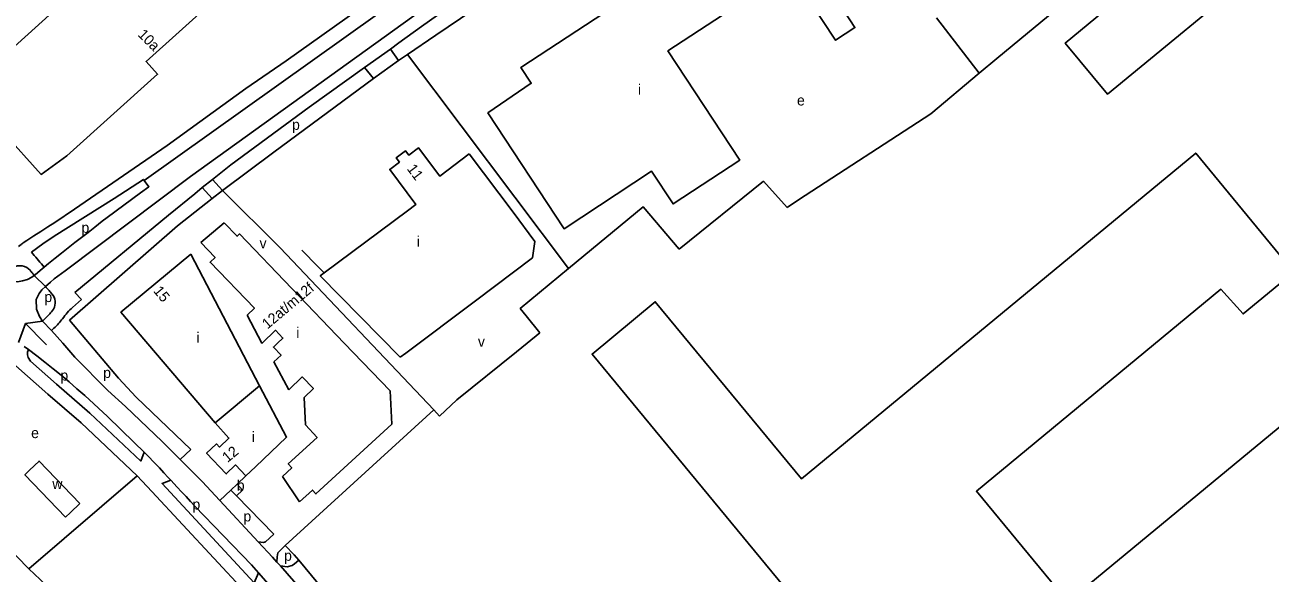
# Model space of a CAD drawing. Extents: x 156097 to 158136, y 385644 to 388348.
# Drawn here: x 156955.8 to 157432.4, y 387161.9 to 387371.8 of the extents above; entities that cross this region are included whole.
import ezdxf

# ---------------------------------------------------------------- set-up
doc = ezdxf.new("R2010")
doc.units = 0
for name, color, linetype in [('BLT_Basislijn', 7, 'Continuous'), ('BLT_Bebouwing', 7, 'Continuous'), ('BLT_Centroide', 7, 'Continuous'), ('BLT_Huisnummer', 7, 'Continuous'), ('BLT_Huisnummer_reeks', 7, 'Continuous'), ('BLT_Onderverdeling_panden', 7, 'Continuous'), ('BLT_Vlakafsluiter', 7, 'Continuous')]:
    doc.layers.add(name, color=color, linetype=linetype)

msp = doc.modelspace()

# ---------------------------------------------------------------- linework, layer by layer
at = {"layer": 'BLT_Basislijn'}
for p, q in [((157411.2, 387428.05), (157327.73, 387358.89)), ((157304.64, 387374.52), (157321.05, 387353.28)), ((157095.67, 387362.5), (157098.81, 387358.08)), ((157102.2, 387360.43), (157163.89, 387278.49)), ((157327.73, 387358.89), (157321.05, 387353.28)), ((157089.23, 387351.22), (157085.74, 387355.5)), ((157321.05, 387353.28), (157302.57, 387337.73)), ((157040.36, 387347.36), (157010.26, 387325.6)), ((157034.53, 387318.15), (157064.57, 387340.26)), ((157251.84, 387304.78), (157302.57, 387337.73)), ((157034.53, 387318.15), (157027.57, 387312.6)), ((157031.44, 387308.36), (157027.57, 387312.6)), ((157206.21, 387285.89), (157238.48, 387311.91)), ((157247.52, 387301.86), (157238.48, 387311.91)), ((157027.5, 387305.26), (157023.66, 387309.47)), ((157027.5, 387305.26), (157031.44, 387308.36)), ((157014.19, 387294.79), (157027.5, 387305.26)), ((157251.84, 387304.78), (157247.52, 387301.86)), ((156972.87, 387258.73), (157014.19, 387294.79)), ((156974.9, 387269.33), (156977.43, 387266.61)), ((157147.6, 387260.39), (157152.82, 387253.94)), ((156963.37, 387250), (156956.03, 387257.5)), ((157152.82, 387253.94), (157148.01, 387250)), ((156964.05, 387249.3), (156963.37, 387250)), ((157015.19, 387205.43), (157008.28, 387212.34)), ((156998.75, 387199.18), (157004.35, 387193.14)), ((157004.35, 387193.14), (157039.88, 387154.84)), ((157051.01, 387176.88), (157036.71, 387191.47)), ((157020.84, 387187.54), (157042.5, 387165.08)), ((157045.08, 387173.87), (157050.48, 387168.05)), ((157050.48, 387168.05), (157052.22, 387166.16)), ((157052.22, 387166.16), (157053.57, 387164.69)), ((157053.57, 387164.69), (157070.1, 387145.87)), ((157072.09, 387152.95), (157060.55, 387166.84))]:
    msp.add_line(p, q, dxfattribs=at)
for points in [[(156963.63, 387271.61), (156965.52, 387273.26), (156967.02, 387274.57), (156971.22, 387277.65), (157019.2, 387313.75), (157135.95, 387397.88), (157205.86, 387444.09), (157219.58, 387453.58), (157239.86, 387466.53), (157269.96, 387483.84), (157285.4, 387492.24)], [(157217.75, 387438.96), (157266.03, 387365.91), (157273.46, 387370.72), (157258.79, 387393.39), (157280.49, 387407.43)], [(157142.41, 387395.65), (157130.75, 387387.73), (157107.59, 387371.12)], [(157040.36, 387347.36), (157055.77, 387358.06), (157101.56, 387390.65)], [(157102.2, 387360.43), (157113.08, 387367.85), (157146.09, 387390.27)], [(157001.46, 387312.19), (157103.63, 387385.12)], [(157107.59, 387371.12), (157098.91, 387364.9)], [(157095.67, 387362.5), (157085.74, 387355.5)], [(157098.91, 387364.9), (157095.67, 387362.5)], [(157089.23, 387351.22), (157098.81, 387358.08)], [(157098.81, 387358.08), (157102.2, 387360.43)], [(157085.74, 387355.5), (157064.57, 387340.26)], [(157031.44, 387308.36), (157051.09, 387323.03), (157089.23, 387351.22)], [(157010.26, 387325.6), (156974.7, 387301.25), (156967.17, 387296.15)], [(156958.26, 387284.77), (156962.63, 387287.92), (156967.02, 387290.9), (156989.97, 387305.26), (157001.13, 387312.64), (157001.46, 387312.19)], [(157001.46, 387312.19), (157003.22, 387309.84), (157000, 387307.49), (156987.27, 387297.99), (156985.28, 387296.58), (156982.55, 387294.3)], [(157023.66, 387309.47), (157027.57, 387312.6)], [(157010.78, 387298.93), (157020.74, 387307.13), (157023.66, 387309.47)], [(157031.44, 387308.36), (157053.42, 387286.46), (157112.23, 387224.4)], [(157163.89, 387278.49), (157192.41, 387302.06), (157206.21, 387285.89)], [(156953.35, 387286.9), (156954.34, 387287.72), (156954.58, 387287.92), (156954.81, 387288.11), (156955.05, 387288.3), (156956.5, 387289.26), (156959.17, 387290.98), (156961.84, 387292.71), (156964.5, 387294.43), (156967.17, 387296.15)], [(156974.9, 387269.33), (157010.78, 387298.93)], [(156963.15, 387279.01), (156964.82, 387280.39), (156967.31, 387282.42), (156969.82, 387284.45), (156972.34, 387286.45), (156974.88, 387288.44), (156977.42, 387290.41), (156979.98, 387292.36), (156982.55, 387294.3)], [(156963.15, 387279.01), (156962.61, 387279.65), (156962.07, 387280.29), (156961.52, 387280.93), (156960.98, 387281.57), (156960.43, 387282.21), (156959.89, 387282.85), (156959.35, 387283.49), (156958.8, 387284.13), (156958.26, 387284.77)], [(157061.82, 387285.58), (157067.85, 387279.3), (157070.04, 387277.14)], [(156950.64, 387278.37), (156951.29, 387278.85), (156952.06, 387279.23), (156952.92, 387279.49), (156953.83, 387279.59), (156954.75, 387279.52), (156955.63, 387279.28), (156956.44, 387278.9), (156957.14, 387278.4), (156957.72, 387277.83)], [(156959.36, 387275.9), (156959.19, 387276.09), (156959.01, 387276.31), (156958.82, 387276.52), (156958.64, 387276.74), (156958.45, 387276.96), (156958.27, 387277.18), (156958.09, 387277.39), (156957.9, 387277.61), (156957.72, 387277.83)], [(156959.87, 387276.27), (156962.34, 387278.34), (156963.15, 387279.01)], [(157070.04, 387277.14), (157070.34, 387276.85)], [(157147.6, 387260.39), (157145.34, 387263.17), (157163.89, 387278.49)], [(156959.36, 387275.9), (156958.42, 387275.22), (156956.74, 387274.36), (156954.9, 387273.76), (156952.94, 387273.47), (156950.95, 387273.5), (156949, 387273.86), (156947.18, 387274.51), (156946.63, 387274.81)], [(156959.87, 387276.27), (156959.36, 387275.9)], [(156962.51, 387258.41), (156961.34, 387260.16), (156960.16, 387263.01), (156960.12, 387266.63), (156961.18, 387268.97), (156962.24, 387270.34), (156963.63, 387271.61)], [(156963.63, 387271.61), (156963.91, 387271.3), (156964.18, 387270.99), (156964.46, 387270.68), (156964.73, 387270.37), (156965.01, 387270.06), (156965.28, 387269.75), (156965.56, 387269.44), (156965.83, 387269.13), (156966.11, 387268.82)], [(156966.29, 387262.41), (156966.7, 387263.01), (156967.03, 387263.7), (156967.25, 387264.45), (156967.36, 387265.24), (156967.34, 387266.05), (156967.18, 387266.84), (156966.92, 387267.57), (156966.55, 387268.24), (156966.11, 387268.82)], [(156966.29, 387262.41), (156965.96, 387261.99), (156965.61, 387261.58), (156965.27, 387261.18), (156964.91, 387260.78), (156964.54, 387260.39), (156964.17, 387260), (156963.8, 387259.62), (156963.41, 387259.25), (156962.51, 387258.41)], [(156970.19, 387259.28), (156970.66, 387259.95), (156971.08, 387260.52), (156971.52, 387261.07), (156971.98, 387261.61), (156972.45, 387262.14), (156972.94, 387262.65), (156973.45, 387263.14), (156973.98, 387263.63), (156977.43, 387266.61)], [(156965.89, 387254.73), (156962.51, 387258.41)], [(156970.19, 387259.28), (156969.83, 387258.83), (156969.43, 387258.35), (156969.02, 387257.87), (156968.6, 387257.41), (156968.18, 387256.95), (156967.74, 387256.5), (156967.3, 387256.06), (156966.86, 387255.63), (156965.89, 387254.73)], [(157019.26, 387209.27), (156998.36, 387229.23), (156991.62, 387236.5), (156972.87, 387258.73)], [(156970.23, 387250), (156965.89, 387254.73)], [(156957.1, 387247.46), (156955.43, 387248.68)], [(156987.49, 387231.8), (156974.86, 387244.61), (156970.23, 387250)], [(157148.01, 387250), (157143.89, 387246.63), (157121.11, 387228.22)], [(156957.1, 387247.46), (156956.78, 387246.51), (156956.73, 387245.46), (156956.99, 387244.44), (156957.86, 387243)], [(156978.64, 387229.87), (156975.67, 387232.5), (156972.66, 387235.1), (156969.62, 387237.65), (156966.54, 387240.17), (156963.42, 387242.64), (156960.28, 387245.07), (156957.1, 387247.46)], [(156952.26, 387241.27), (156964.56, 387230.45), (156977.28, 387219.48), (156998.75, 387199.18)], [(156957.86, 387243), (156967.85, 387234.22), (156980.63, 387223.19), (157000.08, 387204.8), (157001.41, 387208.19)], [(156978.64, 387229.87), (156987.34, 387221.9), (156992.52, 387216.95), (156997.64, 387211.95), (157001.41, 387208.19)], [(156987.49, 387231.8), (156994.29, 387225.72), (157008.28, 387212.34)], [(157055.33, 387172.47), (157112.23, 387224.4)], [(157112.23, 387224.4), (157114.47, 387222.04)], [(157121.11, 387228.22), (157114.47, 387222.04)], [(156915.13, 387206.65), (156957.32, 387163.53)], [(157001.41, 387208.19), (157002.71, 387206.89), (157005.52, 387204.03)], [(157019.26, 387209.27), (157015.19, 387205.43)], [(157015.19, 387205.43), (157023.65, 387196.98), (157030.37, 387189.73)], [(157005.52, 387204.03), (157007.23, 387202.2), (157008.93, 387200.36), (157010.63, 387198.53), (157011.56, 387197.53)], [(156957.32, 387163.53), (156998.75, 387199.18)], [(157011.56, 387197.53), (157008.29, 387196.25), (157043.55, 387158.24), (157045.22, 387162)], [(157011.56, 387197.53), (157014.04, 387194.87), (157015.74, 387193.03), (157017.44, 387191.2), (157019.14, 387189.37), (157020.84, 387187.54)], [(157037.05, 387195.93), (157040.37, 387199.16)], [(157030.37, 387189.73), (157034.64, 387193.66)], [(157030.37, 387189.73), (157045.08, 387173.87)], [(157045.08, 387173.87), (157047.14, 387173.66), (157047.85, 387173.89), (157051.01, 387176.88)], [(157052.22, 387166.16), (157052.28, 387168.18), (157052.57, 387169.63), (157055.33, 387172.47)], [(157060.55, 387166.84), (157058.87, 387168.87), (157055.33, 387172.47)], [(156994.69, 387126.94), (156983.23, 387139.01), (156957.32, 387163.53)], [(157042.5, 387165.08), (157045.22, 387162)], [(157053.57, 387164.69), (157056.18, 387164.3), (157058.04, 387164.79), (157059, 387165.54), (157060.55, 387166.84)], [(157045.22, 387162), (157051.6, 387154.78), (157054.58, 387151.36)]]:
    msp.add_lwpolyline(points, dxfattribs=at)
at = {"layer": 'BLT_Bebouwing'}
for p, q in [((157125.84, 387322.42), (157142.64, 387300.06)), ((157031.99, 387296.02), (157023.07, 387288.52)), ((157040.83, 387260.62), (157046.4, 387250)), ((157046.45, 387249.92), (157046.4, 387250)), ((157046.45, 387249.92), (157046.53, 387250)), ((157101.53, 387246.13), (157099.41, 387244.54)), ((157056.72, 387232.04), (157051.03, 387242.78)), ((157063.17, 387218.74), (157062.65, 387229.2)), ((157034.64, 387193.66), (157037.05, 387195.93)), ((157060.92, 387189.24), (157054.3, 387198.96)), ((157036.71, 387191.47), (157034.64, 387193.66))]:
    msp.add_line(p, q, dxfattribs=at)
for points in [[(157038.09, 387441.53), (156933.03, 387346.62), (156962.04, 387314.53), (156971.84, 387321.61), (157006.52, 387352.89), (157002.13, 387357.76), (157041.29, 387393.15), (157053.38, 387379.77), (157072.5, 387393.4)], [(157218.51, 387427.55), (157243.69, 387389.24), (157201.91, 387361.79), (157229.36, 387320), (157203.83, 387303.22), (157195.6, 387315.75), (157162.16, 387293.75), (157132.98, 387338.1), (157149.58, 387349.4), (157145.56, 387355.42), (157216.58, 387402.06), (157206.77, 387417.03), (157210.94, 387419.78), (157209.65, 387421.72)], [(157414.82, 387415.14), (157353.98, 387364.8), (157370.14, 387345.19), (157431.01, 387395.44)], [(157330.32, 387055.02), (157369.92, 387087.72), (157362.29, 387096.97), (157371.11, 387104.35), (157372.36, 387102.86), (157374.45, 387102.96), (157376.12, 387102.26), (157377.56, 387100.99), (157378.05, 387099.5), (157384.37, 387104.72), (157379.21, 387110.93), (157469.96, 387185.87), (157477.56, 387176.69), (157497.38, 387193.06), (157460.35, 387237.99), (157354.89, 387150.97), (157319.99, 387193.25), (157413.54, 387270.58), (157422.05, 387261.11), (157441.45, 387277.16), (157403.93, 387322.7), (157252.98, 387198.06), (157197.06, 387265.8), (157172.83, 387245.77)]]:
    msp.add_lwpolyline(points, close=True, dxfattribs=at)
for points in [[(157070.34, 387276.85), (157102.26, 387300.64), (157105.45, 387303.03), (157095.38, 387316.43), (157099.13, 387319.26), (157097.87, 387320.94), (157101.4, 387323.57), (157102.66, 387321.9), (157106.4, 387324.73), (157114.52, 387313.92), (157125.84, 387322.42)], [(157078, 387250), (157037.92, 387291.74), (157036.98, 387290.85), (157031.99, 387296.02)], [(157142.64, 387300.06), (157150.96, 387288.91), (157150.05, 387282.59)], [(157023.07, 387288.52), (157028.56, 387282.78), (157026.61, 387280.93), (157043.59, 387263.28), (157040.83, 387260.62)], [(157019.24, 387284.04), (156992.53, 387261.77), (157028.58, 387219.46)], [(157045.54, 387233.64), (157019.24, 387284.04)], [(157150.05, 387282.59), (157128.17, 387266.15), (157101.53, 387246.13)], [(157099.41, 387244.54), (157068.8, 387275.7), (157070.34, 387276.85)], [(157046.53, 387250), (157051.64, 387254.89), (157054.5, 387251.91), (157052.5, 387250)], [(157051.03, 387242.78), (157053.81, 387245.41), (157050.88, 387248.45), (157052.5, 387250)], [(157078, 387250), (157095.58, 387231.69), (157096.19, 387218.9), (157067.13, 387192.22), (157065.78, 387193.68), (157060.92, 387189.24)], [(157062.65, 387229.2), (157066.16, 387232.55), (157061.88, 387237.02), (157056.72, 387232.04)], [(157045.54, 387233.64), (157055.93, 387214), (157043.99, 387202.61), (157040.37, 387199.16)], [(157040.37, 387199.16), (157036.4, 387203.32), (157032.82, 387199.9), (157025.29, 387207.79), (157028.93, 387211.23), (157029.11, 387211.4), (157030.2, 387210.17), (157033.86, 387213.64), (157028.58, 387219.46)], [(157054.3, 387198.96), (157057.93, 387202.26), (157056.57, 387203.73), (157067.6, 387213.88), (157063.17, 387218.74)], [(156971.35, 387183.38), (156955.76, 387199.56), (156957.58, 387201.31), (156961.18, 387204.78), (156976.76, 387188.59)], [(157037.05, 387195.93), (157039.11, 387193.74), (157036.71, 387191.47)], [(156971.35, 387183.38), (156973.16, 387185.13), (156976.76, 387188.59)]]:
    msp.add_lwpolyline(points, dxfattribs=at)
at = {"layer": 'BLT_Onderverdeling_panden'}
msp.add_line((157028.58, 387219.46), (157045.54, 387233.64), dxfattribs=at)
at = {"layer": 'BLT_Vlakafsluiter'}
for p, q in [((156959.36, 387275.9), (156963.63, 387271.61)), ((156956.03, 387257.5), (156962.51, 387258.41)), ((156953.32, 387250.23), (156956.03, 387257.5))]:
    msp.add_line(p, q, dxfattribs=at)

# ---------------------------------------------------------------- texts
at = {"layer": 'BLT_Centroide'}
for s, p in [('i', (157190.39, 387345.02)), ('e', (157251.3, 387340.91)), ('p', (157058.01, 387331.59)), ('p', (156977.42, 387292.18)), ('i', (157105.77, 387286.92)), ('v', (157045.59, 387286.2)), ('p', (156963.21, 387265.67)), ('i', (157021.41, 387250.17)), ('i', (157059.62, 387251.98)), ('v', (157129.16, 387248.57)), ('p', (156969.35, 387235.62)), ('p', (156985.73, 387236.65)), ('e', (156958.15, 387213.6)), ('i', (157042.62, 387212.15)), ('w', (156966.27, 387194.08)), ('b', (157036.88, 387193.53)), ('p', (157019.89, 387186.25)), ('p', (157039.39, 387181.71)), ('p', (157054.97, 387166.65))]:
    msp.add_text(s, height=4, dxfattribs=at).set_placement(p)
at = {"layer": 'BLT_Huisnummer'}
for s, rotation, p in [('10a', 315.1238, (156998.7, 387367.76)), ('11', 306.8914, (157101.79, 387316.64)), ('15', 309.6471, (157004.71, 387269.84)), ('12', 39.6471, (157033.31, 387204.05))]:
    msp.add_text(s, height=4, rotation=rotation, dxfattribs=at).set_placement(p)
at = {"layer": 'BLT_Huisnummer_reeks'}
msp.add_text('12at/m12f', height=4, rotation=40.0322, dxfattribs=at).set_placement((157048.58, 387255.12))

doc.saveas('drawing.dxf')
